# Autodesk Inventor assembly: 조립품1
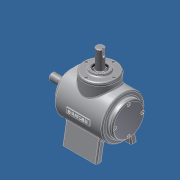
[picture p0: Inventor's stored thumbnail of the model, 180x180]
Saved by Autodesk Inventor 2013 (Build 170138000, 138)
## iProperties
Created: 2015-01
Part Number: 조립품1
Document SubType Name: Assembly
Designer: hanacad21
Author: hanacad21
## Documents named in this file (15)
- C:\Documents and Settings\hanacad21\바탕 화면\450106V1018\조립품1.iam
- C:\Documents and Settings\hanacad21\바탕 화면\450106V1018\본체.ipt
- C:\Documents and Settings\hanacad21\바탕 화면\450106V1018\커버.ipt
- C:\Documents and Settings\hanacad21\바탕 화면\450106V1018\커버2.ipt
- C:\Documents and Settings\hanacad21\바탕 화면\450106V1018\서브 축.ipt
- 서브 축.ipt
- C:\Documents and Settings\hanacad21\바탕 화면\450106V1018\메인 축.ipt
- 메인 축.ipt
- C:\Documents and Settings\hanacad21\바탕 화면\450106V1018\서브 베벨기어.ipt
- C:\Documents and Settings\hanacad21\바탕 화면\450106V1018\메인 베벨기어.ipt
- C:\Documents and Settings\hanacad21\바탕 화면\450106V1018\베어링 6203.ipt
- C:\Documents and Settings\hanacad21\바탕 화면\450106V1018\오일실.ipt
- C:\Documents and Settings\hanacad21\바탕 화면\450106V1018\키 5x5.ipt
- C:\Documents and Settings\hanacad21\바탕 화면\450106V1018\키 4x4.ipt
- C:\Documents and Settings\hanacad21\바탕 화면\450106V1018\M4.ipt
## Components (12 placed, 1 different names)
1. M4:3
2. M4:4
3. M4:5
4. M4:6
5. M4:1
6. M4:7
7. M4:8
8. M4:9
9. M4:2
10. M4:10
11. M4:11
12. M4:12
